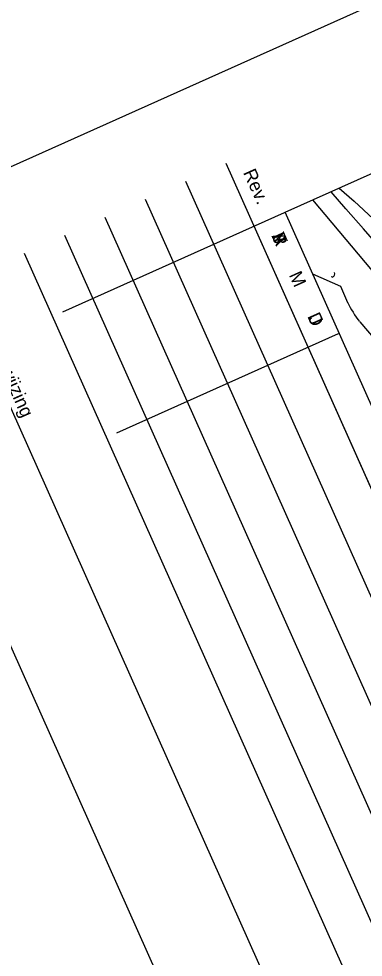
# Model space of a CAD drawing. Extents: x -781656 to -760591, y -1008106 to -975620.
# Drawn here: x -781651.438 to -781650.658, y -1008102.442 to -1008100.32 of the extents above; entities that cross this region are included whole.
import ezdxf

# ---------------------------------------------------------------- set-up
doc = ezdxf.new("R2010")
doc.units = 0
for name, color, linetype in [('Border', 7, 'Continuous'), ('Border_TextCZ', 7, 'Continuous'), ('Border_TextFR', 7, 'Continuous'), ('Border_TextNL', 7, 'Continuous'), ('Border_TextUK', 7, 'Continuous'), ('Koleje_stávající', 7, 'Continuous'), ('Komunikace_stávající_skládka', 7, 'Continuous'), ('SL_05_KOMUNIKACE', 7, 'Continuous')]:
    doc.layers.add(name, color=color, linetype=linetype)

# ---------------------------------------------------------------- blocks, each defined once
blk = doc.blocks.new('A3coversheet_v03_CZ_1_1')
at = {"layer": 'Border'}
blk.add_line((2.1958, 1.5206), (4.0958, 1.5206), dxfattribs=at)
for points in [[(2.1, 0), (2.1, 2.97), (4.2, 2.97)], [(2.2742, 1.5581), (2.2742, 1.2831)], [(2.4242, 1.5581), (2.4242, 1.2831)], [(2.1958, 1.5206), (4.1042, 1.5206)], [(2.1958, 1.4706), (4.1042, 1.4706)], [(2.1958, 1.4206), (4.1042, 1.4206)], [(2.1958, 1.3706), (4.1042, 1.3706)], [(2.1958, 1.3206), (4.1042, 1.3206)], [(2.1958, 1.2706), (4.1042, 1.2706)], [(2.1958, 1.185), (4.1042, 1.185)], [(2.1958, 1.075), (4.1042, 1.075)]]:
    blk.add_lwpolyline(points, dxfattribs=at)
at = {"layer": 'Border_TextCZ'}
for s, p in [('Rev.', (2.2135, 1.534)), ('R', (2.2921, 1.5341)), ('M', (2.3404, 1.5341)), ('D', (2.3915, 1.5341))]:
    blk.add_text(s, height=0.015, dxfattribs=at).set_placement(p)
at = {"layer": 'Border_TextFR'}
for s, p in [('Rev.', (2.2135, 1.534)), ('A', (2.2921, 1.5341)), ('M', (2.3404, 1.5341)), ('J', (2.3939, 1.5341))]:
    blk.add_text(s, height=0.015, dxfattribs=at).set_placement(p)
at = {"layer": 'Border_TextNL'}
for s, p in [('Rev.', (2.2135, 1.534)), ('J', (2.2939, 1.5341)), ('M', (2.3404, 1.5341)), ('D', (2.3915, 1.5341)), ('Externe Verwijzing', (2.1994, 1.1922))]:
    blk.add_text(s, height=0.015, dxfattribs=at).set_placement(p)
at = {"layer": 'Border_TextUK'}
for s, p in [('Rev.', (2.2135, 1.534)), ('Y', (2.2921, 1.5341)), ('M', (2.3404, 1.5341)), ('D', (2.3915, 1.5341))]:
    blk.add_text(s, height=0.015, dxfattribs=at).set_placement(p)
blk = doc.blocks.new('přehledka_1')
at = {"layer": 'Border'}
blk.add_lwpolyline([(0, 0), (0.9992, 0), (0.9992, -0.6522), (0, -0.6522)], close=True, dxfattribs=at)
at = {"layer": 'Koleje_stávající'}
for points in [[(0, -0.5852), (0.0205, -0.5758), (0.0474, -0.564), (0.0889, -0.5458), (0.1161, -0.5338)], [(0.1247, -0.5571), (0.0983, -0.5652), (0.0534, -0.5789), (0.0246, -0.5877), (0, -0.5952)]]:
    blk.add_lwpolyline(points, dxfattribs=at)
at = {"layer": 'Komunikace_stávající_skládka'}
for p, q in [((0.0761, -0.6522), (0.1019, -0.6291)), ((0.0888, -0.6333), (0.0879, -0.6342))]:
    blk.add_line(p, q, dxfattribs=at)
for points in [[(0.1473, -0.6256), (0.1767, -0.617), (0.2034, -0.6091), (0.2526, -0.5944), (0.2763, -0.5873), (0.2924, -0.5823), (0.2965, -0.581), (0.3038, -0.5789), (0.3257, -0.5728), (0.347, -0.5669), (0.3664, -0.561)], [(0.1215, -0.5827), (0, -0.6178)], [(0.1019, -0.6291), (0.1217, -0.6293)]]:
    blk.add_lwpolyline(points, dxfattribs=at)
for centre, radius, start, end in [((0.1182, -0.5135), 0.1158, 271.7433, 284.5242), ((0.0848, -0.633), 0.004, 355.0894, 89.5221)]:
    blk.add_arc(centre, radius, start, end, dxfattribs=at)

msp = doc.modelspace()

# ---------------------------------------------------------------- block references
at = {"layer": 'Border', "xscale": 2.0000000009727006, "yscale": 2.0000000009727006, "rotation": -65.8996989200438}
msp.add_blockref('A3coversheet_v03_CZ_1_1', (-781655.5387, -1008097.8791), dxfattribs=at)
at = {"layer": 'SL_05_KOMUNIKACE', "xscale": 1.999998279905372, "yscale": 1.999998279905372, "rotation": -65.89969891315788}
msp.add_blockref('přehledka_1', (-781649.644, -1008100.2249), dxfattribs=at)

doc.saveas('drawing.dxf')
